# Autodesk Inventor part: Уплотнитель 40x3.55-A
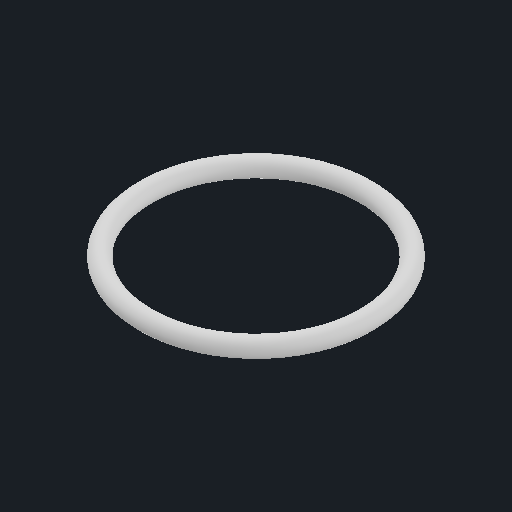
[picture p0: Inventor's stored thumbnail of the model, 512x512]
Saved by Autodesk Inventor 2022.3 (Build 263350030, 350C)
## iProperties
Created: 2020-09
Part Number: Уплотнитель 40x3.55-A
Material: Типовые
Document SubType Name: Modeling
Designer: Карташов
Density: 1 g/cm^3
Appearance: По умолчанию
Title: D:\мои документы\Ирина\_WorldSkills\2020_09 ФНЧ\Module A\Участникам\GIVEN\Уплотнитель 40x3.55-A.stp
Author: Дом
Sending System: Autodesk Inventor 2021
Preprocessor: ST-DEVELOPER v18.1
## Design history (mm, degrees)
feature "Твердое тело2"
node "Твердое тело1"
